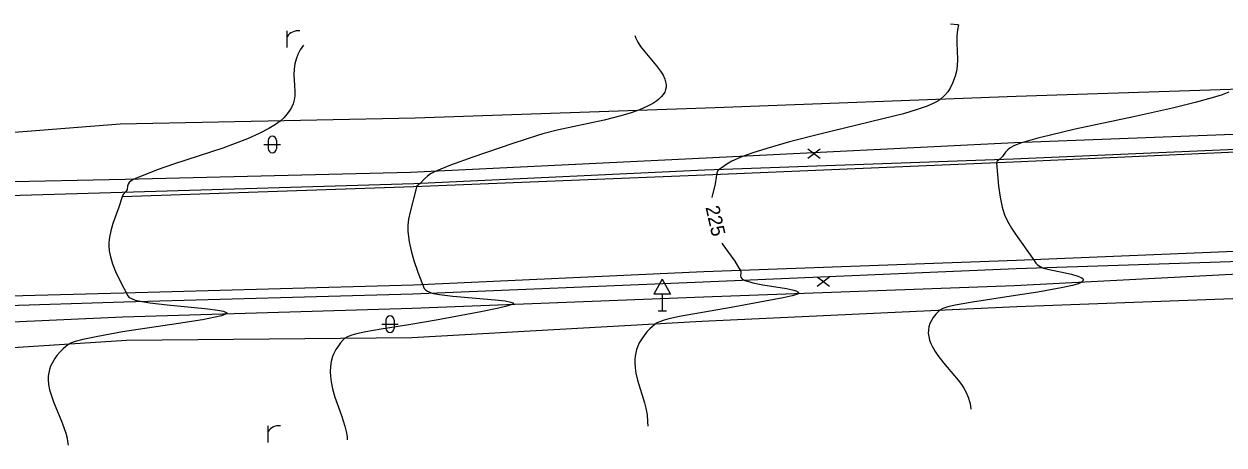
# Model space of a CAD drawing. Extents: x -593772 to -592667, y -1183541 to -1183371.
# Drawn here: x -593611.5 to -593539.2, y -1183403.1 to -1183377.7 of the extents above; entities that cross this region are included whole.
import ezdxf

# ---------------------------------------------------------------- set-up
doc = ezdxf.new("R2010")
doc.units = 0
for name, color, linetype in [('bez obruby', 7, 'Continuous'), ('hlavni vrstevnice', 7, 'Continuous'), ('popis ploch', 7, 'Continuous'), ('svisle dopravni znaceni', 7, 'Continuous'), ('terenni hrany', 7, 'Continuous'), ('vodorovne dopravni znaceni', 7, 'Continuous'), ('vrstevnice', 7, 'Continuous')]:
    doc.layers.add(name, color=color, linetype=linetype)

msp = doc.modelspace()

# ---------------------------------------------------------------- linework, layer by layer
at = {"layer": 'bez obruby'}
for p, q in [((-593534.44, -1183385.09), (-593551.89, -1183385.85)), ((-593551.89, -1183385.85), (-593570.46, -1183386.52)), ((-593570.46, -1183386.52), (-593587.98, -1183387.34)), ((-593587.98, -1183387.34), (-593605.56, -1183387.87)), ((-593605.56, -1183387.87), (-593623.44, -1183388.36)), ((-593534.11, -1183391.25), (-593551.68, -1183391.97)), ((-593551.68, -1183391.97), (-593570.51, -1183392.64)), ((-593570.51, -1183392.64), (-593588, -1183393.45)), ((-593605.48, -1183393.94), (-593623.56, -1183394.39)), ((-593588, -1183393.45), (-593605.48, -1183393.94))]:
    msp.add_line(p, q, dxfattribs=at)
at = {"layer": 'hlavni vrstevnice'}
for points in [[(-593555.654, -1183377.696), (-593555.242, -1183377.729), (-593555.183, -1183377.748), (-593555.241, -1183378.047), (-593555.274, -1183378.412), (-593555.275, -1183378.856), (-593555.237, -1183379.819), (-593555.255, -1183380.232), (-593555.299, -1183380.551), (-593555.37, -1183380.84), (-593555.528, -1183381.27), (-593555.679, -1183381.568), (-593555.821, -1183381.784), (-593555.998, -1183381.994), (-593556.29, -1183382.269), (-593556.416, -1183382.358), (-593556.651, -1183382.483), (-593557.058, -1183382.657), (-593557.66, -1183382.865), (-593558.489, -1183383.108), (-593559.725, -1183383.425), (-593561.303, -1183383.799), (-593563.534, -1183384.339), (-593565.345, -1183384.813), (-593566.717, -1183385.205), (-593567.566, -1183385.476), (-593568.18, -1183385.697), (-593568.836, -1183385.978), (-593569.136, -1183386.151), (-593569.601, -1183386.492), (-593569.688, -1183386.581), (-593569.732, -1183386.678), (-593569.767, -1183386.935), (-593569.841, -1183387.348), (-593570.038, -1183388.164)], [(-593569.424, -1183390.92), (-593569.243, -1183391.182), (-593568.65, -1183392.009), (-593568.417, -1183392.38), (-593568.315, -1183392.566), (-593568.293, -1183392.625), (-593568.29, -1183392.73), (-593568.306, -1183392.898), (-593568.284, -1183392.981), (-593568.229, -1183393.053), (-593568.126, -1183393.124), (-593568.038, -1183393.163), (-593567.738, -1183393.262), (-593567.557, -1183393.31), (-593566.97, -1183393.424), (-593565.533, -1183393.661), (-593565.089, -1183393.761), (-593564.916, -1183393.82), (-593564.842, -1183393.863), (-593564.816, -1183393.893), (-593564.811, -1183393.923), (-593564.844, -1183393.969), (-593564.92, -1183394.011), (-593565.188, -1183394.097), (-593565.743, -1183394.22), (-593568.858, -1183394.794), (-593571.986, -1183395.352), (-593572.63, -1183395.494), (-593572.902, -1183395.57), (-593573.187, -1183395.666), (-593573.378, -1183395.754), (-593573.476, -1183395.822), (-593573.76, -1183396.087), (-593573.939, -1183396.275), (-593574.117, -1183396.492), (-593574.289, -1183396.742), (-593574.4, -1183396.936), (-593574.492, -1183397.131), (-593574.564, -1183397.328), (-593574.619, -1183397.526), (-593574.655, -1183397.727), (-593574.675, -1183397.929), (-593574.68, -1183398.133), (-593574.658, -1183398.44), (-593574.61, -1183398.754), (-593574.51, -1183399.176), (-593574.084, -1183400.553), (-593574.008, -1183400.865), (-593573.936, -1183401.282), (-593573.898, -1183401.696), (-593573.89, -1183401.961)]]:
    msp.add_lwpolyline(points, dxfattribs=at)
at = {"layer": 'popis ploch'}
for p, q in [((-593595.61, -1183379.12), (-593595.61, -1183378.12)), ((-593597.01, -1183384.97), (-593596.01, -1183384.97)), ((-593596.76, -1183384.72), (-593596.76, -1183385.22)), ((-593596.26, -1183384.72), (-593596.26, -1183385.22)), ((-593589.92, -1183395.81), (-593588.92, -1183395.81)), ((-593589.67, -1183395.56), (-593589.67, -1183396.06)), ((-593589.17, -1183395.56), (-593589.17, -1183396.06)), ((-593596.76, -1183402.94), (-593596.76, -1183401.94))]:
    msp.add_line(p, q, dxfattribs=at)
for centre, radius, start, end in [((-593594.973, -1183378.857), 0.746, 81.32683, 148.70696), ((-593596.511, -1183384.72), 0.25, 0, 180), ((-593596.511, -1183385.22), 0.25, 180, 0), ((-593589.421, -1183395.56), 0.25, 0, 180), ((-593589.421, -1183396.06), 0.25, 180, 0), ((-593596.123, -1183402.677), 0.746, 81.32683, 148.70696)]:
    msp.add_arc(centre, radius, start, end, dxfattribs=at)
at = {"layer": 'svisle dopravni znaceni'}
for p, q in [((-593564.255, -1183385.801), (-593563.505, -1183385.238)), ((-593564.255, -1183385.238), (-593563.505, -1183385.801)), ((-593573.02, -1183393.1), (-593573.52, -1183394)), ((-593573.02, -1183393.1), (-593572.52, -1183394)), ((-593563.695, -1183393.511), (-593562.945, -1183392.948)), ((-593563.695, -1183392.948), (-593562.945, -1183393.511)), ((-593572.52, -1183394), (-593573.52, -1183394)), ((-593573.02, -1183394), (-593573.02, -1183395)), ((-593573.27, -1183395), (-593572.77, -1183395))]:
    msp.add_line(p, q, dxfattribs=at)
at = {"layer": 'terenni hrany'}
for p, q in [((-593534.88, -1183381.52), (-593551.71, -1183382.08)), ((-593551.71, -1183382.08), (-593569.83, -1183382.76)), ((-593569.83, -1183382.76), (-593587.9, -1183383.37)), ((-593605.68, -1183383.75), (-593623.7, -1183385.13)), ((-593587.9, -1183383.37), (-593605.68, -1183383.75)), ((-593534.51, -1183384.22), (-593551.8, -1183384.86)), ((-593551.8, -1183384.86), (-593570.38, -1183385.8)), ((-593570.38, -1183385.8), (-593588.19, -1183386.66)), ((-593588.19, -1183386.66), (-593605.37, -1183387.08)), ((-593605.37, -1183387.08), (-593623.54, -1183387.46)), ((-593534.05, -1183391.89), (-593551.71, -1183392.47)), ((-593551.71, -1183392.47), (-593570.55, -1183393.27)), ((-593534.01, -1183392.56), (-593551.8, -1183393.5)), ((-593570.55, -1183393.27), (-593588.05, -1183394)), ((-593588.05, -1183394), (-593605.45, -1183394.48)), ((-593551.8, -1183393.5), (-593570.53, -1183394.17)), ((-593605.45, -1183394.48), (-593623.46, -1183395.04)), ((-593570.53, -1183394.17), (-593588.08, -1183394.86)), ((-593551.65, -1183394.76), (-593570.64, -1183395.65)), ((-593533.98, -1183394.1), (-593551.65, -1183394.76)), ((-593605.52, -1183395.39), (-593623.43, -1183396.17)), ((-593588.08, -1183394.86), (-593605.52, -1183395.39)), ((-593570.64, -1183395.65), (-593588.11, -1183396.64)), ((-593605.29, -1183396.79), (-593623.39, -1183397.98)), ((-593588.11, -1183396.64), (-593605.29, -1183396.79))]:
    msp.add_line(p, q, dxfattribs=at)
at = {"layer": 'vodorovne dopravni znaceni'}
for p, q in [((-593534.44, -1183385.25), (-593551.87, -1183386.03)), ((-593551.87, -1183386.03), (-593570.45, -1183386.82)), ((-593570.45, -1183386.82), (-593588, -1183387.53)), ((-593588, -1183387.53), (-593605.55, -1183388.12))]:
    msp.add_line(p, q, dxfattribs=at)
at = {"layer": 'vrstevnice'}
for points in [[(-593574.676, -1183378.389), (-593574.614, -1183378.562), (-593574.494, -1183378.8), (-593574.324, -1183379.057), (-593574.078, -1183379.373), (-593573.357, -1183380.222), (-593573.123, -1183380.538), (-593572.969, -1183380.793), (-593572.863, -1183381.03), (-593572.816, -1183381.19), (-593572.791, -1183381.347), (-593572.791, -1183381.502), (-593572.818, -1183381.655), (-593572.873, -1183381.806), (-593572.959, -1183381.955), (-593573.076, -1183382.1), (-593573.224, -1183382.238), (-593573.336, -1183382.327), (-593573.584, -1183382.489), (-593573.94, -1183382.678), (-593574.399, -1183382.881), (-593574.884, -1183383.057), (-593575.51, -1183383.241), (-593576.523, -1183383.491), (-593579.342, -1183384.107), (-593580.213, -1183384.324), (-593580.536, -1183384.418), (-593582.023, -1183384.9), (-593584.42, -1183385.724), (-593585.779, -1183386.222), (-593586.698, -1183386.594), (-593586.975, -1183386.734), (-593587.168, -1183386.869), (-593587.347, -1183387.043), (-593587.606, -1183387.315), (-593587.798, -1183387.482), (-593587.823, -1183387.537), (-593588.212, -1183389.026), (-593588.3, -1183389.479), (-593588.34, -1183389.843), (-593588.34, -1183390.208), (-593588.258, -1183390.838), (-593588.145, -1183391.375), (-593587.985, -1183391.961), (-593587.743, -1183392.665), (-593587.357, -1183393.653), (-593587.28, -1183393.742), (-593587.159, -1183393.821), (-593586.944, -1183393.908), (-593586.795, -1183393.95), (-593586.428, -1183394.018), (-593585.634, -1183394.108), (-593583.087, -1183394.329), (-593582.475, -1183394.403), (-593582.137, -1183394.47), (-593582.022, -1183394.512), (-593581.988, -1183394.541), (-593581.986, -1183394.569), (-593582.014, -1183394.598), (-593582.079, -1183394.63), (-593582.381, -1183394.729), (-593582.97, -1183394.871), (-593583.939, -1183395.065), (-593586.631, -1183395.559), (-593588.283, -1183395.844), (-593589.949, -1183396.102), (-593590.869, -1183396.268), (-593591.447, -1183396.396), (-593591.711, -1183396.468), (-593591.936, -1183396.544), (-593592.105, -1183396.625), (-593592.145, -1183396.655), (-593592.236, -1183396.746), (-593592.393, -1183396.928), (-593592.531, -1183397.112), (-593592.676, -1183397.341), (-593592.795, -1183397.574), (-593592.873, -1183397.767), (-593592.96, -1183398.064), (-593593.01, -1183398.358), (-593593.027, -1183398.662), (-593593.013, -1183398.971), (-593592.972, -1183399.282), (-593592.88, -1183399.705), (-593592.734, -1183400.202), (-593592.346, -1183401.324), (-593592.134, -1183401.969), (-593592.055, -1183402.283), (-593592.003, -1183402.599), (-593591.99, -1183402.777)], [(-593594.629, -1183378.969), (-593594.824, -1183379.253), (-593594.972, -1183379.534), (-593595.081, -1183379.819), (-593595.153, -1183380.109), (-593595.192, -1183380.403), (-593595.205, -1183380.777), (-593595.168, -1183381.382), (-593595.143, -1183381.786), (-593595.155, -1183382.029), (-593595.191, -1183382.272), (-593595.261, -1183382.511), (-593595.36, -1183382.744), (-593595.447, -1183382.898), (-593595.609, -1183383.12), (-593595.816, -1183383.349), (-593596.044, -1183383.557), (-593596.319, -1183383.76), (-593596.722, -1183384.005), (-593597.304, -1183384.302), (-593598.009, -1183384.616), (-593598.745, -1183384.911), (-593599.499, -1183385.179), (-593602.409, -1183386.131), (-593603.442, -1183386.496), (-593604.291, -1183386.828), (-593604.841, -1183387.068), (-593605.018, -1183387.167), (-593605.129, -1183387.264), (-593605.19, -1183387.358), (-593605.226, -1183387.49), (-593605.26, -1183387.687), (-593605.315, -1183387.793), (-593605.487, -1183387.985), (-593605.55, -1183388.12), (-593605.757, -1183388.75), (-593606.113, -1183389.737), (-593606.244, -1183390.186), (-593606.318, -1183390.549), (-593606.352, -1183390.879), (-593606.354, -1183391.083), (-593606.328, -1183391.391), (-593606.257, -1183391.753), (-593606.133, -1183392.166), (-593605.948, -1183392.638), (-593605.673, -1183393.214), (-593605.208, -1183394.099), (-593605.124, -1183394.188), (-593604.996, -1183394.267), (-593604.763, -1183394.355), (-593604.347, -1183394.449), (-593603.88, -1183394.518), (-593602.833, -1183394.634), (-593600.57, -1183394.855), (-593599.798, -1183394.958), (-593599.447, -1183395.031), (-593599.32, -1183395.075), (-593599.27, -1183395.105), (-593599.249, -1183395.135), (-593599.259, -1183395.166), (-593599.325, -1183395.211), (-593599.56, -1183395.296), (-593599.946, -1183395.392), (-593600.715, -1183395.54), (-593602.154, -1183395.769), (-593605.536, -1183396.27), (-593607.02, -1183396.544), (-593607.925, -1183396.737), (-593608.379, -1183396.854), (-593608.666, -1183396.954), (-593608.81, -1183397.035), (-593609.116, -1183397.3), (-593609.307, -1183397.489), (-593609.493, -1183397.705), (-593609.614, -1183397.869), (-593609.779, -1183398.15), (-593609.866, -1183398.346), (-593609.932, -1183398.542), (-593609.977, -1183398.741), (-593610.002, -1183398.941), (-593610.008, -1183399.143), (-593609.983, -1183399.448), (-593609.926, -1183399.761), (-593609.839, -1183400.069), (-593609.689, -1183400.49), (-593609.169, -1183401.763), (-593608.956, -1183402.384), (-593608.874, -1183402.688), (-593608.836, -1183402.891), (-593608.815, -1183403.098)], [(-593538.881, -1183381.81), (-593539.299, -1183381.969), (-593539.899, -1183382.162), (-593540.914, -1183382.441), (-593542.273, -1183382.771), (-593544.64, -1183383.294), (-593548.147, -1183384.052), (-593549.633, -1183384.399), (-593550.403, -1183384.594), (-593551.383, -1183384.871), (-593551.807, -1183385.029), (-593552.053, -1183385.163), (-593552.205, -1183385.281), (-593552.338, -1183385.433), (-593552.528, -1183385.7), (-593552.69, -1183385.851), (-593552.749, -1183385.897), (-593552.859, -1183386.002), (-593552.886, -1183386.072), (-593552.763, -1183387.488), (-593552.673, -1183388.142), (-593552.545, -1183388.75), (-593552.506, -1183388.897), (-593552.394, -1183389.213), (-593552.22, -1183389.59), (-593551.973, -1183390.021), (-593551.744, -1183390.371), (-593550.607, -1183391.956), (-593550.508, -1183392.131), (-593550.408, -1183392.237), (-593550.263, -1183392.335), (-593550.051, -1183392.425), (-593549.787, -1183392.491), (-593548.365, -1183392.8), (-593547.98, -1183392.911), (-593547.786, -1183392.993), (-593547.693, -1183393.059), (-593547.658, -1183393.11), (-593547.656, -1183393.161), (-593547.682, -1183393.213), (-593547.784, -1183393.293), (-593547.975, -1183393.372), (-593548.315, -1183393.467), (-593548.99, -1183393.614), (-593550.401, -1183393.867), (-593551.741, -1183394.086), (-593554.34, -1183394.473), (-593555.368, -1183394.659), (-593555.81, -1183394.767), (-593556.118, -1183394.87), (-593556.3, -1183394.97), (-593556.543, -1183395.212), (-593556.692, -1183395.398), (-593556.809, -1183395.586), (-593556.897, -1183395.775), (-593556.956, -1183395.968), (-593556.988, -1183396.162), (-593556.991, -1183396.359), (-593556.969, -1183396.56), (-593556.92, -1183396.763), (-593556.846, -1183396.97), (-593556.748, -1183397.18), (-593556.586, -1183397.459), (-593556.418, -1183397.706), (-593556.076, -1183398.147), (-593555.199, -1183399.185), (-593554.995, -1183399.455), (-593554.851, -1183399.673), (-593554.733, -1183399.888), (-593554.593, -1183400.217), (-593554.496, -1183400.529), (-593554.455, -1183400.738), (-593554.432, -1183400.935)]]:
    msp.add_lwpolyline(points, dxfattribs=at)

# ---------------------------------------------------------------- texts
at = {"layer": 'hlavni vrstevnice'}
msp.add_text('225', height=0.8351, rotation=282.75602, dxfattribs=at).set_placement((-593570.421, -1183388.752))

doc.saveas('drawing.dxf')
